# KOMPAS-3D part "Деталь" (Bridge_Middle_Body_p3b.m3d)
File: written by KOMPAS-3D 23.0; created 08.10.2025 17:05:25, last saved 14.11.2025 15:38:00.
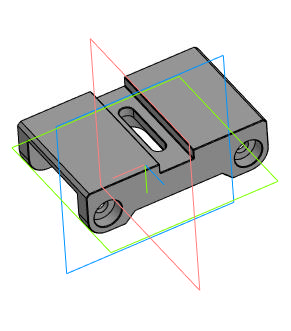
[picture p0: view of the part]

Document properties: Автор: ADMIN; Полное имя файла: D:\YandexDisk\Model\NVG\ARM mkII\Bridge Middle Body p3b.m3d

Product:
- Part/product: Деталь
    Масса: 0.115412

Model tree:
1. Эскиз:1
2. Элемент выдавливания:1
     Расстояние 1 = 35
3. Эскиз:10  (with: Элемент выдавливания:1)
4. Элемент выдавливания:10
     Расстояние 2 = 12.1
5. Эскиз:2  (with: Элемент выдавливания:1)
6. Элемент выдавливания:2
     Расстояние 2 = 12.1
7. Эскиз:3  (with: Элемент выдавливания:1)
8. Элемент выдавливания:3
     Расстояние 2 = 3
9. Эскиз:4  (with: Элемент выдавливания:1)
10. Элемент выдавливания:4
     Расстояние 2 = 35
11. Эскиз:5  (with: Элемент выдавливания:3)
12. Элемент выдавливания:5
13. Эскиз:6  (with: Элемент выдавливания:4, Элемент выдавливания:3)
14. Элемент выдавливания:6
     Расстояние 2 = 6
15. Эскиз:7  (with: Элемент выдавливания:1)
16. Элемент выдавливания:7
     Расстояние 2 = 3.5
17. Эскиз:8  (with: Элемент выдавливания:1)
18. Элемент выдавливания:8
     Расстояние 2 = 3.5
19. Эскиз:9  (with: Элемент выдавливания:1)
20. Элемент выдавливания:9
     Расстояние 2 = 0.5
21. Скругление:1  (with: Элемент выдавливания:1, Элемент выдавливания:10, Элемент выдавливания:2)
     Радиус = 5.5
22. Скругление:2  (with: Элемент выдавливания:5)
     Радиус = 2
23. Скругление:3  (with: Элемент выдавливания:6)
     Радиус = 5
24. Фаска:1  (with: Элемент выдавливания:4)
     Угол = 45; Длина 1 = 3; Длина 2 = 3
25. Фаска:2  (with: Фаска:1, Элемент выдавливания:1)
     Угол = 45; Длина 1 = 1; Длина 2 = 1
26. Фаска:3  (with: Элемент выдавливания:6, Элемент выдавливания:3, Фаска:1, Элемент выдавливания:10, Скругление:1, Элемент выдавливания:2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)
     Угол = 45; Длина 1 = 0.2; Длина 2 = 0.2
